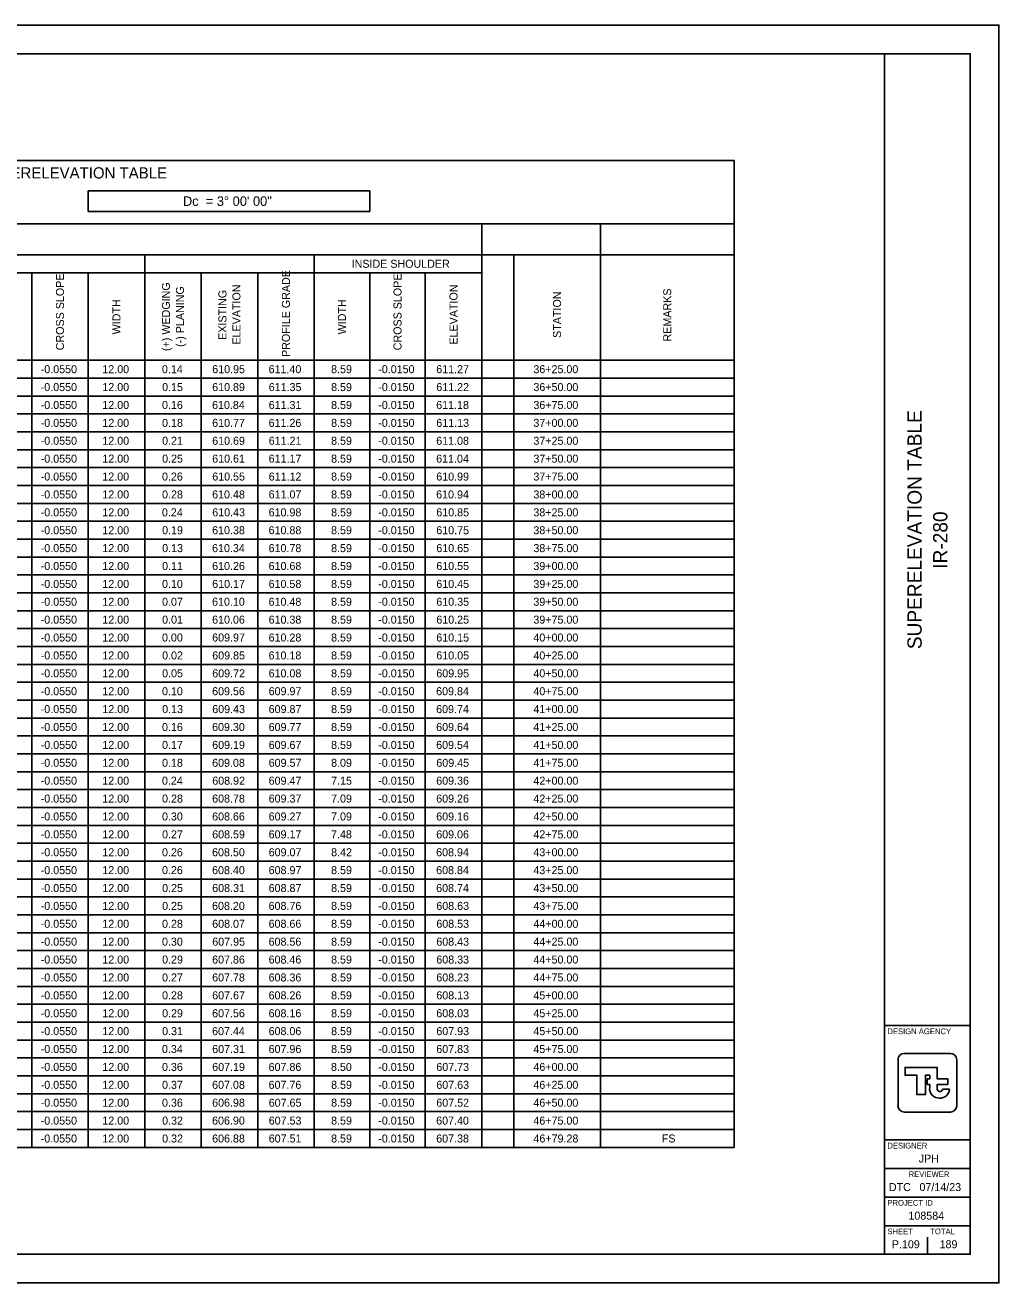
# Model space of a CAD drawing. Extents: x 0 to 34, y 0 to 22.
# Drawn here: x 16.97 to 34, y 0 to 22 of the extents above; entities that cross this region are included whole.
import ezdxf

# ---------------------------------------------------------------- set-up
doc = ezdxf.new("R2010")
doc.units = 0
for name, color, linetype in [('Default', 7, 'Continuous'), ('SH_Border', 7, 'Continuous'), ('SH_Cut_Line', 7, 'Continuous'), ('SH_Data', 7, 'Continuous')]:
    doc.layers.add(name, color=color, linetype=linetype)

msp = doc.modelspace()

# ---------------------------------------------------------------- linework, layer by layer
at = {"layer": 'Default'}
for p, q in [((4.135, 19.63), (29.368, 19.63)), ((29.368, 19.63), (29.368, 2.369)), ((18.069, 19.103), (22.994, 19.103)), ((18.069, 19.103), (18.069, 18.741)), ((22.994, 19.103), (22.994, 18.741)), ((18.069, 18.741), (22.994, 18.741)), ((4.135, 18.526), (29.368, 18.526)), ((24.954, 18.526), (24.954, 2.369)), ((27.029, 18.526), (27.029, 2.369)), ((4.135, 17.983), (29.368, 17.983)), ((19.057, 17.983), (19.057, 2.369)), ((22.022, 17.983), (22.022, 2.369)), ((25.514, 17.983), (25.514, 2.369)), ((4.135, 17.67), (24.954, 17.67)), ((17.081, 17.67), (17.081, 2.369)), ((18.069, 17.67), (18.069, 2.369)), ((20.046, 17.67), (20.046, 2.369)), ((21.034, 17.67), (21.034, 2.369)), ((22.994, 17.67), (22.994, 2.369)), ((23.966, 17.67), (23.966, 2.369)), ((4.135, 16.138), (29.368, 16.138)), ((4.135, 15.825), (29.368, 15.825)), ((4.135, 15.512), (29.368, 15.512)), ((4.135, 15.199), (29.368, 15.199)), ((4.135, 14.886), (29.368, 14.886)), ((4.135, 14.574), (29.368, 14.574)), ((4.135, 14.261), (29.368, 14.261)), ((4.135, 13.948), (29.368, 13.948)), ((4.135, 13.635), (29.368, 13.635)), ((4.135, 13.322), (29.368, 13.322)), ((4.135, 13.009), (29.368, 13.009)), ((4.135, 12.696), (29.368, 12.696)), ((4.135, 12.383), (29.368, 12.383)), ((4.135, 12.07), (29.368, 12.07)), ((4.135, 11.757), (29.368, 11.757)), ((4.135, 11.444), (29.368, 11.444)), ((4.135, 11.131), (29.368, 11.131)), ((4.135, 10.818), (29.368, 10.818)), ((4.135, 10.505), (29.368, 10.505)), ((4.135, 10.192), (29.368, 10.192)), ((4.135, 9.879), (29.368, 9.879)), ((4.135, 9.566), (29.368, 9.566)), ((4.135, 9.254), (29.368, 9.254)), ((4.135, 8.941), (29.368, 8.941)), ((4.135, 8.628), (29.368, 8.628)), ((4.135, 8.315), (29.368, 8.315)), ((4.135, 8.002), (29.368, 8.002)), ((4.135, 7.689), (29.368, 7.689)), ((4.135, 7.376), (29.368, 7.376)), ((4.135, 7.063), (29.368, 7.063)), ((4.135, 6.75), (29.368, 6.75)), ((4.135, 6.437), (29.368, 6.437)), ((4.135, 6.124), (29.368, 6.124)), ((4.135, 5.811), (29.368, 5.811)), ((4.135, 5.498), (29.368, 5.498)), ((4.135, 5.185), (29.368, 5.185)), ((4.135, 4.872), (29.368, 4.872)), ((4.135, 4.559), (29.368, 4.559)), ((4.135, 4.246), (29.368, 4.246)), ((4.135, 3.934), (29.368, 3.934)), ((4.135, 3.621), (29.368, 3.621)), ((4.135, 3.308), (29.368, 3.308)), ((4.135, 2.995), (29.368, 2.995)), ((4.135, 2.682), (29.368, 2.682)), ((4.135, 2.369), (29.368, 2.369))]:
    msp.add_line(p, q, dxfattribs=at)
at = {"layer": 'SH_Border'}
for p, q in [((32, 0.5), (32, 21.5)), ((32, 4.5), (33.5, 4.5)), ((32, 2.5), (33.5, 2.5)), ((32, 2), (33.5, 2)), ((32, 1.5), (33.5, 1.5)), ((32, 1), (33.5, 1))]:
    msp.add_line(p, q, dxfattribs=at)
msp.add_lwpolyline([(1.5, 21.5), (33.5, 21.5), (33.5, 0.5), (1.5, 0.5)], close=True, dxfattribs=at)
at = {"layer": 'SH_Cut_Line'}
msp.add_lwpolyline([(0, 0), (34, 0), (34, 22), (0, 22)], close=True, dxfattribs=at)
at = {"layer": 'SH_Data'}
for p, q in [((32.75, 3.5), (32.75, 3.5)), ((32.791, 3.415), (32.791, 3.415)), ((33.136, 3.385), (33.015, 3.385)), ((32.375, 0.675), (32.375, 0.675)), ((32.75, 0.5), (32.75, 0.8))]:
    msp.add_line(p, q, dxfattribs=at)
for points in [[(32.348, 4.014), (33.152, 4.014)], [(32.236, 3.099), (32.236, 3.901)], [(32.922, 3.399), (32.922, 3.47), (33.107, 3.47), (33.107, 3.568), (32.922, 3.568), (32.922, 3.768), (32.361, 3.768), (32.361, 3.632), (32.566, 3.632), (32.566, 3.294), (32.715, 3.294), (32.715, 3.63), (32.79, 3.63), (32.79, 3.568), (32.748, 3.568), (32.748, 3.47), (32.79, 3.47), (32.79, 3.415), (32.791, 3.415)], [(33.264, 3.901), (33.264, 3.099)], [(33.152, 2.986), (32.348, 2.986)]]:
    msp.add_lwpolyline(points, dxfattribs=at)
for centre, radius, start, end in [((32.348, 3.901), 0.113, 90, 180), ((33.152, 3.901), 0.113, 360, 90), ((32.949, 3.392), 0.16, 171.8856, 274.8323), ((32.968, 3.392), 0.0473, 171.8856, 350.9243), ((32.976, 3.392), 0.16, 265.1677, 357.3201), ((32.348, 3.099), 0.113, 180, 270), ((33.152, 3.099), 0.113, 270, 360)]:
    msp.add_arc(centre, radius, start, end, dxfattribs=at)

# ---------------------------------------------------------------- texts
at = {"layer": 'Default'}
for s, height, p in [('WOO/LUC-280-06.20/00.00 - SUPERELEVATION TABLE', 0.196, (12.689, 19.318)), ('Dc  = 3° 00\' 00"', 0.168, (19.726, 18.838)), ('INSIDE SHOULDER', 0.14, (22.678, 17.756)), ('-0.0550', 0.14, (17.238, 15.912)), ('12.00', 0.14, (18.316, 15.912)), ('0.14', 0.14, (19.359, 15.912)), ('610.95', 0.14, (20.239, 15.912)), ('611.40', 0.14, (21.225, 15.912)), ('8.59', 0.14, (22.318, 15.912)), ('-0.0150', 0.14, (23.143, 15.912)), ('611.27', 0.14, (24.158, 15.912)), ('36+25.00', 0.14, (25.857, 15.912)), ('-0.0550', 0.14, (17.238, 15.599)), ('12.00', 0.14, (18.316, 15.599)), ('0.15', 0.14, (19.362, 15.599)), ('610.89', 0.14, (20.238, 15.599)), ('611.35', 0.14, (21.227, 15.599)), ('8.59', 0.14, (22.318, 15.599)), ('-0.0150', 0.14, (23.143, 15.599)), ('611.22', 0.14, (24.159, 15.599)), ('36+50.00', 0.14, (25.857, 15.599)), ('-0.0550', 0.14, (17.238, 15.286)), ('12.00', 0.14, (18.316, 15.286)), ('0.16', 0.14, (19.36, 15.286)), ('610.84', 0.14, (20.236, 15.286)), ('611.31', 0.14, (21.227, 15.286)), ('8.59', 0.14, (22.318, 15.286)), ('-0.0150', 0.14, (23.143, 15.286)), ('611.18', 0.14, (24.157, 15.286)), ('36+75.00', 0.14, (25.857, 15.286)), ('-0.0550', 0.14, (17.238, 14.973)), ('12.00', 0.14, (18.316, 14.973)), ('0.18', 0.14, (19.361, 14.973)), ('610.77', 0.14, (20.238, 14.973)), ('611.26', 0.14, (21.225, 14.973)), ('8.59', 0.14, (22.318, 14.973)), ('-0.0150', 0.14, (23.143, 14.973)), ('611.13', 0.14, (24.159, 14.973)), ('37+00.00', 0.14, (25.857, 14.973)), ('-0.0550', 0.14, (17.238, 14.66)), ('12.00', 0.14, (18.316, 14.66)), ('0.21', 0.14, (19.362, 14.66)), ('610.69', 0.14, (20.238, 14.66)), ('611.21', 0.14, (21.227, 14.66)), ('8.59', 0.14, (22.318, 14.66)), ('-0.0150', 0.14, (23.143, 14.66)), ('611.08', 0.14, (24.157, 14.66)), ('37+25.00', 0.14, (25.857, 14.66)), ('-0.0550', 0.14, (17.238, 14.347)), ('12.00', 0.14, (18.316, 14.347)), ('0.25', 0.14, (19.362, 14.347)), ('610.61', 0.14, (20.238, 14.347)), ('611.17', 0.14, (21.226, 14.347)), ('8.59', 0.14, (22.318, 14.347)), ('-0.0150', 0.14, (23.143, 14.347)), ('611.04', 0.14, (24.156, 14.347)), ('37+50.00', 0.14, (25.857, 14.347)), ('-0.0550', 0.14, (17.238, 14.034)), ('12.00', 0.14, (18.316, 14.034)), ('0.26', 0.14, (19.36, 14.034)), ('610.55', 0.14, (20.239, 14.034)), ('611.12', 0.14, (21.227, 14.034)), ('8.59', 0.14, (22.318, 14.034)), ('-0.0150', 0.14, (23.143, 14.034)), ('610.99', 0.14, (24.158, 14.034)), ('37+75.00', 0.14, (25.857, 14.034)), ('-0.0550', 0.14, (17.238, 13.721)), ('12.00', 0.14, (18.316, 13.721)), ('0.28', 0.14, (19.361, 13.721)), ('610.48', 0.14, (20.237, 13.721)), ('611.07', 0.14, (21.226, 13.721)), ('8.59', 0.14, (22.318, 13.721)), ('-0.0150', 0.14, (23.143, 13.721)), ('610.94', 0.14, (24.156, 13.721)), ('38+00.00', 0.14, (25.857, 13.721)), ('-0.0550', 0.14, (17.238, 13.408)), ('12.00', 0.14, (18.316, 13.408)), ('0.24', 0.14, (19.359, 13.408)), ('610.43', 0.14, (20.239, 13.408)), ('610.98', 0.14, (21.225, 13.408)), ('8.59', 0.14, (22.318, 13.408)), ('-0.0150', 0.14, (23.143, 13.408)), ('610.85', 0.14, (24.159, 13.408)), ('38+25.00', 0.14, (25.857, 13.408)), ('-0.0550', 0.14, (17.238, 13.095)), ('12.00', 0.14, (18.316, 13.095)), ('0.19', 0.14, (19.362, 13.095)), ('610.38', 0.14, (20.237, 13.095)), ('610.88', 0.14, (21.225, 13.095)), ('8.59', 0.14, (22.318, 13.095)), ('-0.0150', 0.14, (23.143, 13.095)), ('610.75', 0.14, (24.159, 13.095)), ('38+50.00', 0.14, (25.857, 13.095)), ('-0.0550', 0.14, (17.238, 12.782)), ('12.00', 0.14, (18.316, 12.782)), ('0.13', 0.14, (19.363, 12.782)), ('610.34', 0.14, (20.236, 12.782)), ('610.78', 0.14, (21.225, 12.782)), ('8.59', 0.14, (22.318, 12.782)), ('-0.0150', 0.14, (23.143, 12.782)), ('610.65', 0.14, (24.159, 12.782)), ('38+75.00', 0.14, (25.857, 12.782)), ('-0.0550', 0.14, (17.238, 12.469)), ('12.00', 0.14, (18.316, 12.469)), ('0.11', 0.14, (19.362, 12.469)), ('610.26', 0.14, (20.237, 12.469)), ('610.68', 0.14, (21.225, 12.469)), ('8.59', 0.14, (22.318, 12.469)), ('-0.0150', 0.14, (23.143, 12.469)), ('610.55', 0.14, (24.159, 12.469)), ('39+00.00', 0.14, (25.857, 12.469)), ('-0.0550', 0.14, (17.238, 12.156)), ('12.00', 0.14, (18.316, 12.156)), ('0.10', 0.14, (19.36, 12.156)), ('610.17', 0.14, (20.238, 12.156)), ('610.58', 0.14, (21.225, 12.156)), ('8.59', 0.14, (22.318, 12.156)), ('-0.0150', 0.14, (23.143, 12.156)), ('610.45', 0.14, (24.159, 12.156)), ('39+25.00', 0.14, (25.857, 12.156)), ('-0.0550', 0.14, (17.238, 11.844)), ('12.00', 0.14, (18.316, 11.844)), ('0.07', 0.14, (19.361, 11.844)), ('610.10', 0.14, (20.236, 11.844)), ('610.48', 0.14, (21.225, 11.844)), ('8.59', 0.14, (22.318, 11.844)), ('-0.0150', 0.14, (23.143, 11.844)), ('610.35', 0.14, (24.159, 11.844)), ('39+50.00', 0.14, (25.857, 11.844)), ('-0.0550', 0.14, (17.238, 11.531)), ('12.00', 0.14, (18.316, 11.531)), ('0.01', 0.14, (19.362, 11.531)), ('610.06', 0.14, (20.237, 11.531)), ('610.38', 0.14, (21.225, 11.531)), ('8.59', 0.14, (22.318, 11.531)), ('-0.0150', 0.14, (23.143, 11.531)), ('610.25', 0.14, (24.159, 11.531)), ('39+75.00', 0.14, (25.857, 11.531)), ('-0.0550', 0.14, (17.238, 11.218)), ('12.00', 0.14, (18.316, 11.218)), ('0.00', 0.14, (19.36, 11.218)), ('609.97', 0.14, (20.238, 11.218)), ('610.28', 0.14, (21.225, 11.218)), ('8.59', 0.14, (22.318, 11.218)), ('-0.0150', 0.14, (23.143, 11.218)), ('610.15', 0.14, (24.159, 11.218)), ('40+00.00', 0.14, (25.857, 11.218)), ('-0.0550', 0.14, (17.238, 10.905)), ('12.00', 0.14, (18.316, 10.905)), ('0.02', 0.14, (19.362, 10.905)), ('609.85', 0.14, (20.239, 10.905)), ('610.18', 0.14, (21.225, 10.905)), ('8.59', 0.14, (22.318, 10.905)), ('-0.0150', 0.14, (23.143, 10.905)), ('610.05', 0.14, (24.159, 10.905)), ('40+25.00', 0.14, (25.857, 10.905)), ('-0.0550', 0.14, (17.238, 10.592)), ('12.00', 0.14, (18.316, 10.592)), ('0.05', 0.14, (19.362, 10.592)), ('609.72', 0.14, (20.239, 10.592)), ('610.08', 0.14, (21.225, 10.592)), ('8.59', 0.14, (22.318, 10.592)), ('-0.0150', 0.14, (23.143, 10.592)), ('609.95', 0.14, (24.159, 10.592)), ('40+50.00', 0.14, (25.857, 10.592)), ('-0.0550', 0.14, (17.238, 10.279)), ('12.00', 0.14, (18.316, 10.279)), ('0.10', 0.14, (19.36, 10.279)), ('609.56', 0.14, (20.237, 10.279)), ('609.97', 0.14, (21.226, 10.279)), ('8.59', 0.14, (22.318, 10.279)), ('-0.0150', 0.14, (23.143, 10.279)), ('609.84', 0.14, (24.156, 10.279)), ('40+75.00', 0.14, (25.857, 10.279)), ('-0.0550', 0.14, (17.238, 9.966)), ('12.00', 0.14, (18.316, 9.966)), ('0.13', 0.14, (19.363, 9.966)), ('609.43', 0.14, (20.239, 9.966)), ('609.87', 0.14, (21.226, 9.966)), ('8.59', 0.14, (22.318, 9.966)), ('-0.0150', 0.14, (23.143, 9.966)), ('609.74', 0.14, (24.156, 9.966)), ('41+00.00', 0.14, (25.857, 9.966)), ('-0.0550', 0.14, (17.238, 9.653)), ('12.00', 0.14, (18.316, 9.653)), ('0.16', 0.14, (19.36, 9.653)), ('609.30', 0.14, (20.236, 9.653)), ('609.77', 0.14, (21.226, 9.653)), ('8.59', 0.14, (22.318, 9.653)), ('-0.0150', 0.14, (23.143, 9.653)), ('609.64', 0.14, (24.156, 9.653)), ('41+25.00', 0.14, (25.857, 9.653)), ('-0.0550', 0.14, (17.238, 9.34)), ('12.00', 0.14, (18.316, 9.34)), ('0.17', 0.14, (19.361, 9.34)), ('609.19', 0.14, (20.238, 9.34)), ('609.67', 0.14, (21.226, 9.34)), ('8.59', 0.14, (22.318, 9.34)), ('-0.0150', 0.14, (23.143, 9.34)), ('609.54', 0.14, (24.156, 9.34)), ('41+50.00', 0.14, (25.857, 9.34)), ('-0.0550', 0.14, (17.238, 9.027)), ('12.00', 0.14, (18.316, 9.027)), ('0.18', 0.14, (19.361, 9.027)), ('609.08', 0.14, (20.237, 9.027)), ('609.57', 0.14, (21.226, 9.027)), ('8.09', 0.14, (22.318, 9.027)), ('-0.0150', 0.14, (23.143, 9.027)), ('609.45', 0.14, (24.159, 9.027)), ('41+75.00', 0.14, (25.857, 9.027)), ('-0.0550', 0.14, (17.238, 8.714)), ('12.00', 0.14, (18.316, 8.714)), ('0.24', 0.14, (19.359, 8.714)), ('608.92', 0.14, (20.239, 8.714)), ('609.47', 0.14, (21.226, 8.714)), ('7.15', 0.14, (22.319, 8.714)), ('-0.0150', 0.14, (23.143, 8.714)), ('609.36', 0.14, (24.157, 8.714)), ('42+00.00', 0.14, (25.857, 8.714)), ('-0.0550', 0.14, (17.238, 8.401)), ('12.00', 0.14, (18.316, 8.401)), ('0.28', 0.14, (19.361, 8.401)), ('608.78', 0.14, (20.237, 8.401)), ('609.37', 0.14, (21.226, 8.401)), ('7.09', 0.14, (22.318, 8.401)), ('-0.0150', 0.14, (23.143, 8.401)), ('609.26', 0.14, (24.157, 8.401)), ('42+25.00', 0.14, (25.857, 8.401)), ('-0.0550', 0.14, (17.238, 8.088)), ('12.00', 0.14, (18.316, 8.088)), ('0.30', 0.14, (19.36, 8.088)), ('608.66', 0.14, (20.237, 8.088)), ('609.27', 0.14, (21.226, 8.088)), ('7.09', 0.14, (22.318, 8.088)), ('-0.0150', 0.14, (23.143, 8.088)), ('609.16', 0.14, (24.157, 8.088)), ('42+50.00', 0.14, (25.857, 8.088)), ('-0.0550', 0.14, (17.238, 7.775)), ('12.00', 0.14, (18.316, 7.775)), ('0.27', 0.14, (19.361, 7.775)), ('608.59', 0.14, (20.238, 7.775)), ('609.17', 0.14, (21.226, 7.775)), ('7.48', 0.14, (22.317, 7.775)), ('-0.0150', 0.14, (23.143, 7.775)), ('609.06', 0.14, (24.157, 7.775)), ('42+75.00', 0.14, (25.857, 7.775)), ('-0.0550', 0.14, (17.238, 7.462)), ('12.00', 0.14, (18.316, 7.462)), ('0.26', 0.14, (19.36, 7.462)), ('608.50', 0.14, (20.236, 7.462)), ('609.07', 0.14, (21.226, 7.462)), ('8.42', 0.14, (22.319, 7.462)), ('-0.0150', 0.14, (23.143, 7.462)), ('608.94', 0.14, (24.156, 7.462)), ('43+00.00', 0.14, (25.857, 7.462)), ('-0.0550', 0.14, (17.238, 7.149)), ('12.00', 0.14, (18.316, 7.149)), ('0.26', 0.14, (19.36, 7.149)), ('608.40', 0.14, (20.236, 7.149)), ('608.97', 0.14, (21.226, 7.149)), ('8.59', 0.14, (22.318, 7.149)), ('-0.0150', 0.14, (23.143, 7.149)), ('608.84', 0.14, (24.156, 7.149)), ('43+25.00', 0.14, (25.857, 7.149)), ('-0.0550', 0.14, (17.238, 6.836)), ('12.00', 0.14, (18.316, 6.836)), ('0.25', 0.14, (19.362, 6.836)), ('608.31', 0.14, (20.238, 6.836)), ('608.87', 0.14, (21.226, 6.836)), ('8.59', 0.14, (22.318, 6.836)), ('-0.0150', 0.14, (23.143, 6.836)), ('608.74', 0.14, (24.156, 6.836)), ('43+50.00', 0.14, (25.857, 6.836)), ('-0.0550', 0.14, (17.238, 6.524)), ('12.00', 0.14, (18.316, 6.524)), ('0.25', 0.14, (19.362, 6.524)), ('608.20', 0.14, (20.236, 6.524)), ('608.76', 0.14, (21.225, 6.524)), ('8.59', 0.14, (22.318, 6.524)), ('-0.0150', 0.14, (23.143, 6.524)), ('608.63', 0.14, (24.159, 6.524)), ('43+75.00', 0.14, (25.857, 6.524)), ('-0.0550', 0.14, (17.238, 6.211)), ('12.00', 0.14, (18.316, 6.211)), ('0.28', 0.14, (19.361, 6.211)), ('608.07', 0.14, (20.238, 6.211)), ('608.66', 0.14, (21.225, 6.211)), ('8.59', 0.14, (22.318, 6.211)), ('-0.0150', 0.14, (23.143, 6.211)), ('608.53', 0.14, (24.159, 6.211)), ('44+00.00', 0.14, (25.857, 6.211)), ('-0.0550', 0.14, (17.238, 5.898)), ('12.00', 0.14, (18.316, 5.898)), ('0.30', 0.14, (19.36, 5.898)), ('607.95', 0.14, (20.239, 5.898)), ('608.56', 0.14, (21.225, 5.898)), ('8.59', 0.14, (22.318, 5.898)), ('-0.0150', 0.14, (23.143, 5.898)), ('608.43', 0.14, (24.159, 5.898)), ('44+25.00', 0.14, (25.857, 5.898)), ('-0.0550', 0.14, (17.238, 5.585)), ('12.00', 0.14, (18.316, 5.585)), ('0.29', 0.14, (19.362, 5.585)), ('607.86', 0.14, (20.237, 5.585)), ('608.46', 0.14, (21.225, 5.585)), ('8.59', 0.14, (22.318, 5.585)), ('-0.0150', 0.14, (23.143, 5.585)), ('608.33', 0.14, (24.159, 5.585)), ('44+50.00', 0.14, (25.857, 5.585)), ('-0.0550', 0.14, (17.238, 5.272)), ('12.00', 0.14, (18.316, 5.272)), ('0.27', 0.14, (19.361, 5.272)), ('607.78', 0.14, (20.237, 5.272)), ('608.36', 0.14, (21.225, 5.272)), ('8.59', 0.14, (22.318, 5.272)), ('-0.0150', 0.14, (23.143, 5.272)), ('608.23', 0.14, (24.159, 5.272)), ('44+75.00', 0.14, (25.857, 5.272)), ('-0.0550', 0.14, (17.238, 4.959)), ('12.00', 0.14, (18.316, 4.959)), ('0.28', 0.14, (19.361, 4.959)), ('607.67', 0.14, (20.238, 4.959)), ('608.26', 0.14, (21.225, 4.959)), ('8.59', 0.14, (22.318, 4.959)), ('-0.0150', 0.14, (23.143, 4.959)), ('608.13', 0.14, (24.159, 4.959)), ('45+00.00', 0.14, (25.857, 4.959)), ('-0.0550', 0.14, (17.238, 4.646)), ('12.00', 0.14, (18.316, 4.646)), ('0.29', 0.14, (19.362, 4.646)), ('607.56', 0.14, (20.237, 4.646)), ('608.16', 0.14, (21.225, 4.646)), ('8.59', 0.14, (22.318, 4.646)), ('-0.0150', 0.14, (23.143, 4.646)), ('608.03', 0.14, (24.159, 4.646)), ('45+25.00', 0.14, (25.857, 4.646)), ('-0.0550', 0.14, (17.238, 4.333)), ('12.00', 0.14, (18.316, 4.333)), ('0.31', 0.14, (19.362, 4.333)), ('607.44', 0.14, (20.236, 4.333)), ('608.06', 0.14, (21.225, 4.333)), ('8.59', 0.14, (22.318, 4.333)), ('-0.0150', 0.14, (23.143, 4.333)), ('607.93', 0.14, (24.159, 4.333)), ('45+50.00', 0.14, (25.857, 4.333)), ('-0.0550', 0.14, (17.238, 4.02)), ('12.00', 0.14, (18.316, 4.02)), ('0.34', 0.14, (19.359, 4.02)), ('607.31', 0.14, (20.238, 4.02)), ('607.96', 0.14, (21.225, 4.02)), ('8.59', 0.14, (22.318, 4.02)), ('-0.0150', 0.14, (23.143, 4.02)), ('607.83', 0.14, (24.159, 4.02)), ('45+75.00', 0.14, (25.857, 4.02)), ('-0.0550', 0.14, (17.238, 3.707)), ('12.00', 0.14, (18.316, 3.707)), ('0.36', 0.14, (19.36, 3.707)), ('607.19', 0.14, (20.238, 3.707)), ('607.86', 0.14, (21.225, 3.707)), ('8.50', 0.14, (22.316, 3.707)), ('-0.0150', 0.14, (23.143, 3.707)), ('607.73', 0.14, (24.159, 3.707)), ('46+00.00', 0.14, (25.857, 3.707)), ('-0.0550', 0.14, (17.238, 3.394)), ('12.00', 0.14, (18.316, 3.394)), ('0.37', 0.14, (19.361, 3.394)), ('607.08', 0.14, (20.237, 3.394)), ('607.76', 0.14, (21.225, 3.394)), ('8.59', 0.14, (22.318, 3.394)), ('-0.0150', 0.14, (23.143, 3.394)), ('607.63', 0.14, (24.159, 3.394)), ('46+25.00', 0.14, (25.857, 3.394)), ('-0.0550', 0.14, (17.238, 3.081)), ('12.00', 0.14, (18.316, 3.081)), ('0.36', 0.14, (19.36, 3.081)), ('606.98', 0.14, (20.237, 3.081)), ('607.65', 0.14, (21.227, 3.081)), ('8.59', 0.14, (22.318, 3.081)), ('-0.0150', 0.14, (23.143, 3.081)), ('607.52', 0.14, (24.159, 3.081)), ('46+50.00', 0.14, (25.857, 3.081)), ('-0.0550', 0.14, (17.238, 2.768)), ('12.00', 0.14, (18.316, 2.768)), ('0.32', 0.14, (19.362, 2.768)), ('606.90', 0.14, (20.236, 2.768)), ('607.53', 0.14, (21.227, 2.768)), ('8.59', 0.14, (22.318, 2.768)), ('-0.0150', 0.14, (23.143, 2.768)), ('607.40', 0.14, (24.156, 2.768)), ('46+75.00', 0.14, (25.857, 2.768)), ('-0.0550', 0.14, (17.238, 2.455)), ('12.00', 0.14, (18.316, 2.455)), ('0.32', 0.14, (19.362, 2.455)), ('606.88', 0.14, (20.237, 2.455)), ('607.51', 0.14, (21.227, 2.455)), ('8.59', 0.14, (22.318, 2.455)), ('-0.0150', 0.14, (23.143, 2.455)), ('607.38', 0.14, (24.157, 2.455)), ('46+79.28', 0.14, (25.858, 2.455)), ('FS', 0.14, (28.103, 2.455))]:
    msp.add_text(s, height=height, dxfattribs=at).set_placement(p)
for s, p in [('CROSS SLOPE', (17.645, 16.313)), ('PROFILE GRADE', (21.598, 16.196)), ('CROSS SLOPE', (23.55, 16.313)), ('(+) WEDGING', (19.499, 16.3)), ('(-) PLANING', (19.744, 16.372)), ('ELEVATION', (20.732, 16.413)), ('ELEVATION', (24.53, 16.413)), ('REMARKS', (28.269, 16.467)), ('WIDTH', (18.633, 16.591)), ('EXISTING ', (20.487, 16.495)), ('WIDTH', (22.578, 16.591)), ('STATION', (26.341, 16.53))]:
    msp.add_text(s, height=0.14, rotation=90, dxfattribs=at).set_placement(p)
at = {"layer": 'SH_Data'}
for s, p in [('SUPERELEVATION TABLE', (32.65, 11.084)), ('IR-280', (33.1, 12.491))]:
    msp.add_text(s, height=0.25, rotation=90, dxfattribs=at).set_placement(p)
for s, height, p in [('DESIGN AGENCY', 0.1, (32.05, 4.35)), ('DESIGNER', 0.1, (32.05, 2.35)), ('JPH', 0.14, (32.598, 2.105)), ('REVIEWER', 0.1, (32.422, 1.85)), ('DTC', 0.14, (32.076, 1.605)), ('07/14/23', 0.14, (32.611, 1.605)), ('PROJECT ID', 0.1, (32.05, 1.35)), ('108584', 0.14, (32.418, 1.105)), ('SHEET', 0.1, (32.05, 0.85)), ('TOTAL', 0.1, (32.8, 0.85)), ('P.109', 0.14, (32.128, 0.605)), ('189', 0.14, (32.963, 0.605))]:
    msp.add_text(s, height=height, dxfattribs=at).set_placement(p)

doc.saveas('drawing.dxf')
